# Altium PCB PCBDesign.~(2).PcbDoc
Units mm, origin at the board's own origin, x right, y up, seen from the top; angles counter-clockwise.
Board outline 60 x 50 mm, 2 copper layers (Top Layer, Bottom Layer); 10 components, 6 nets, 31 pads, 0 vias.
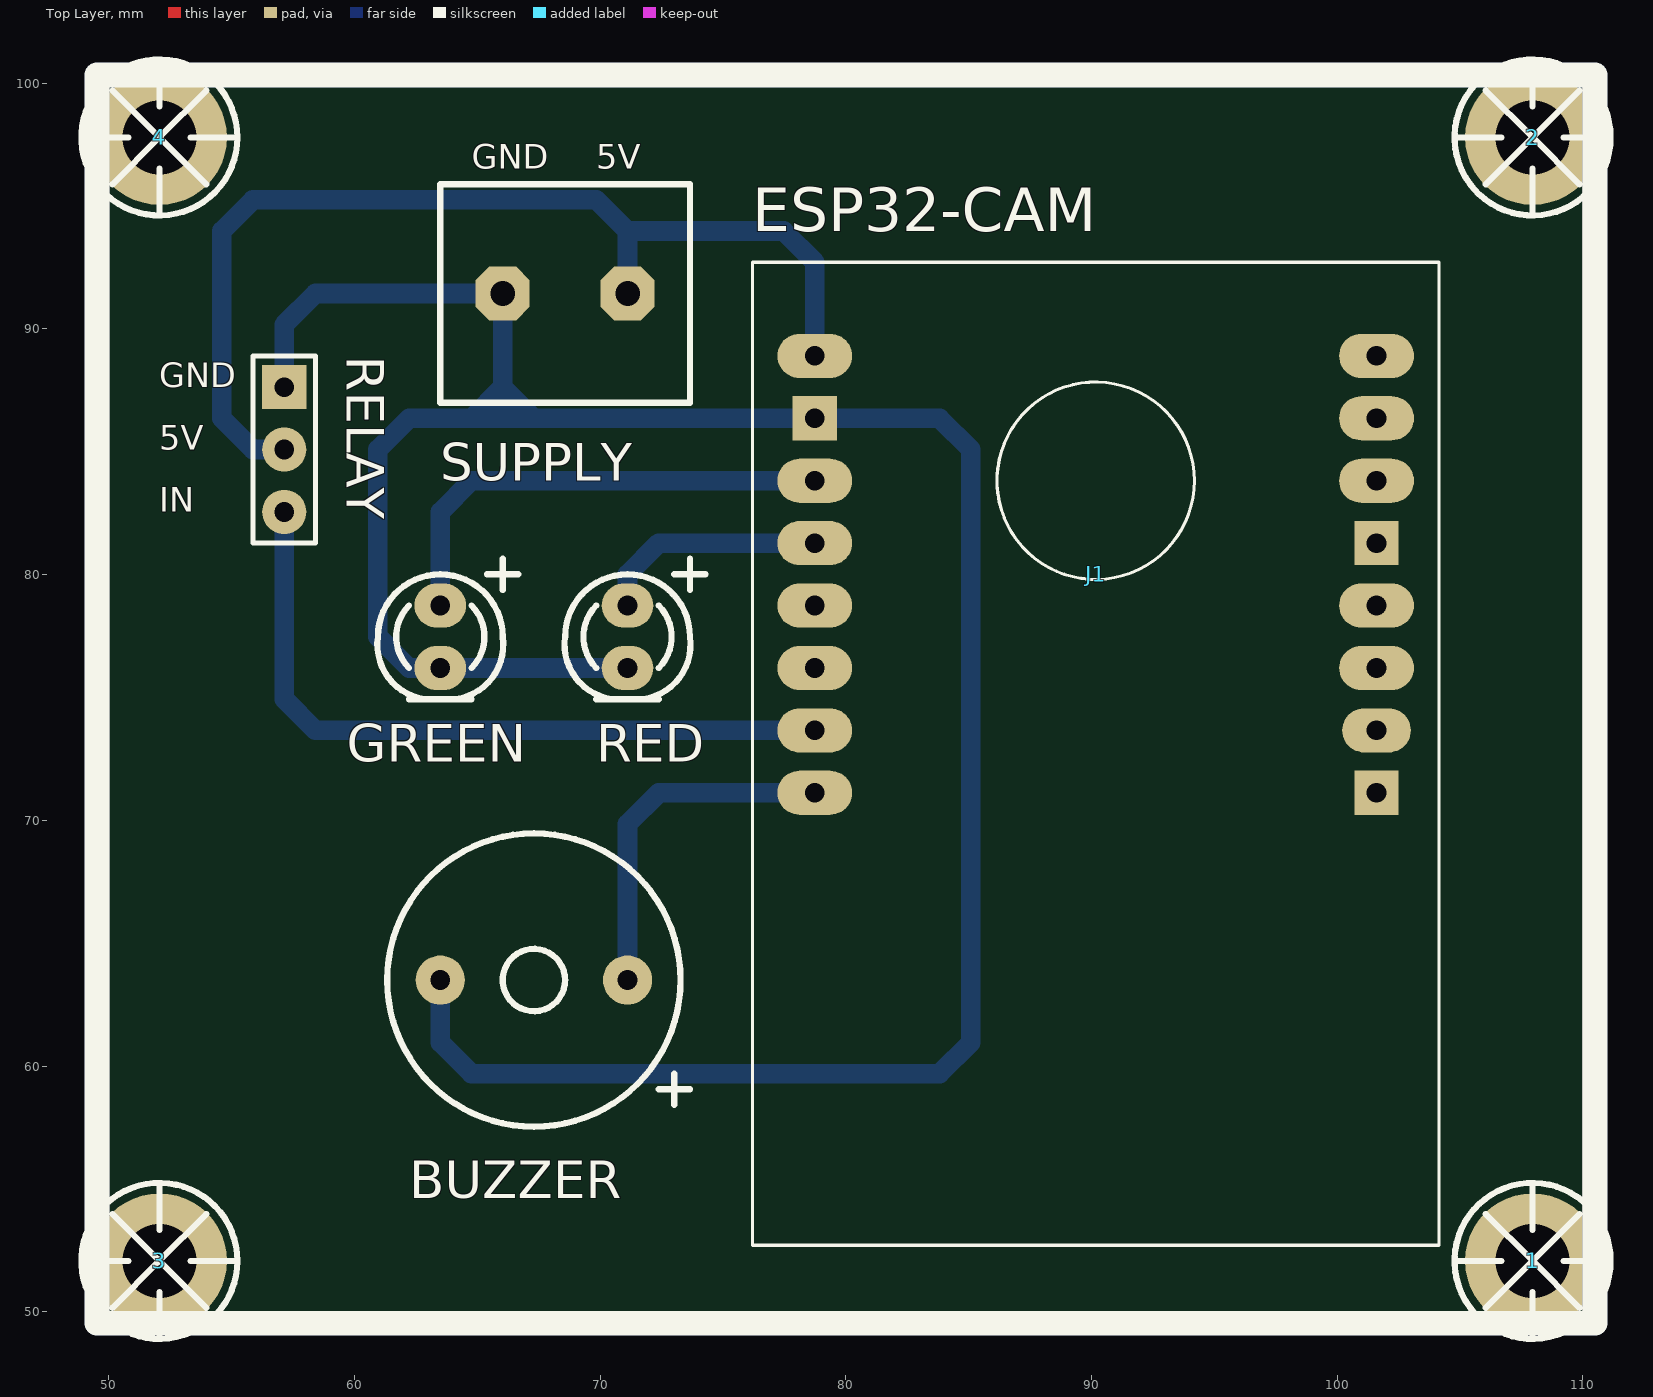
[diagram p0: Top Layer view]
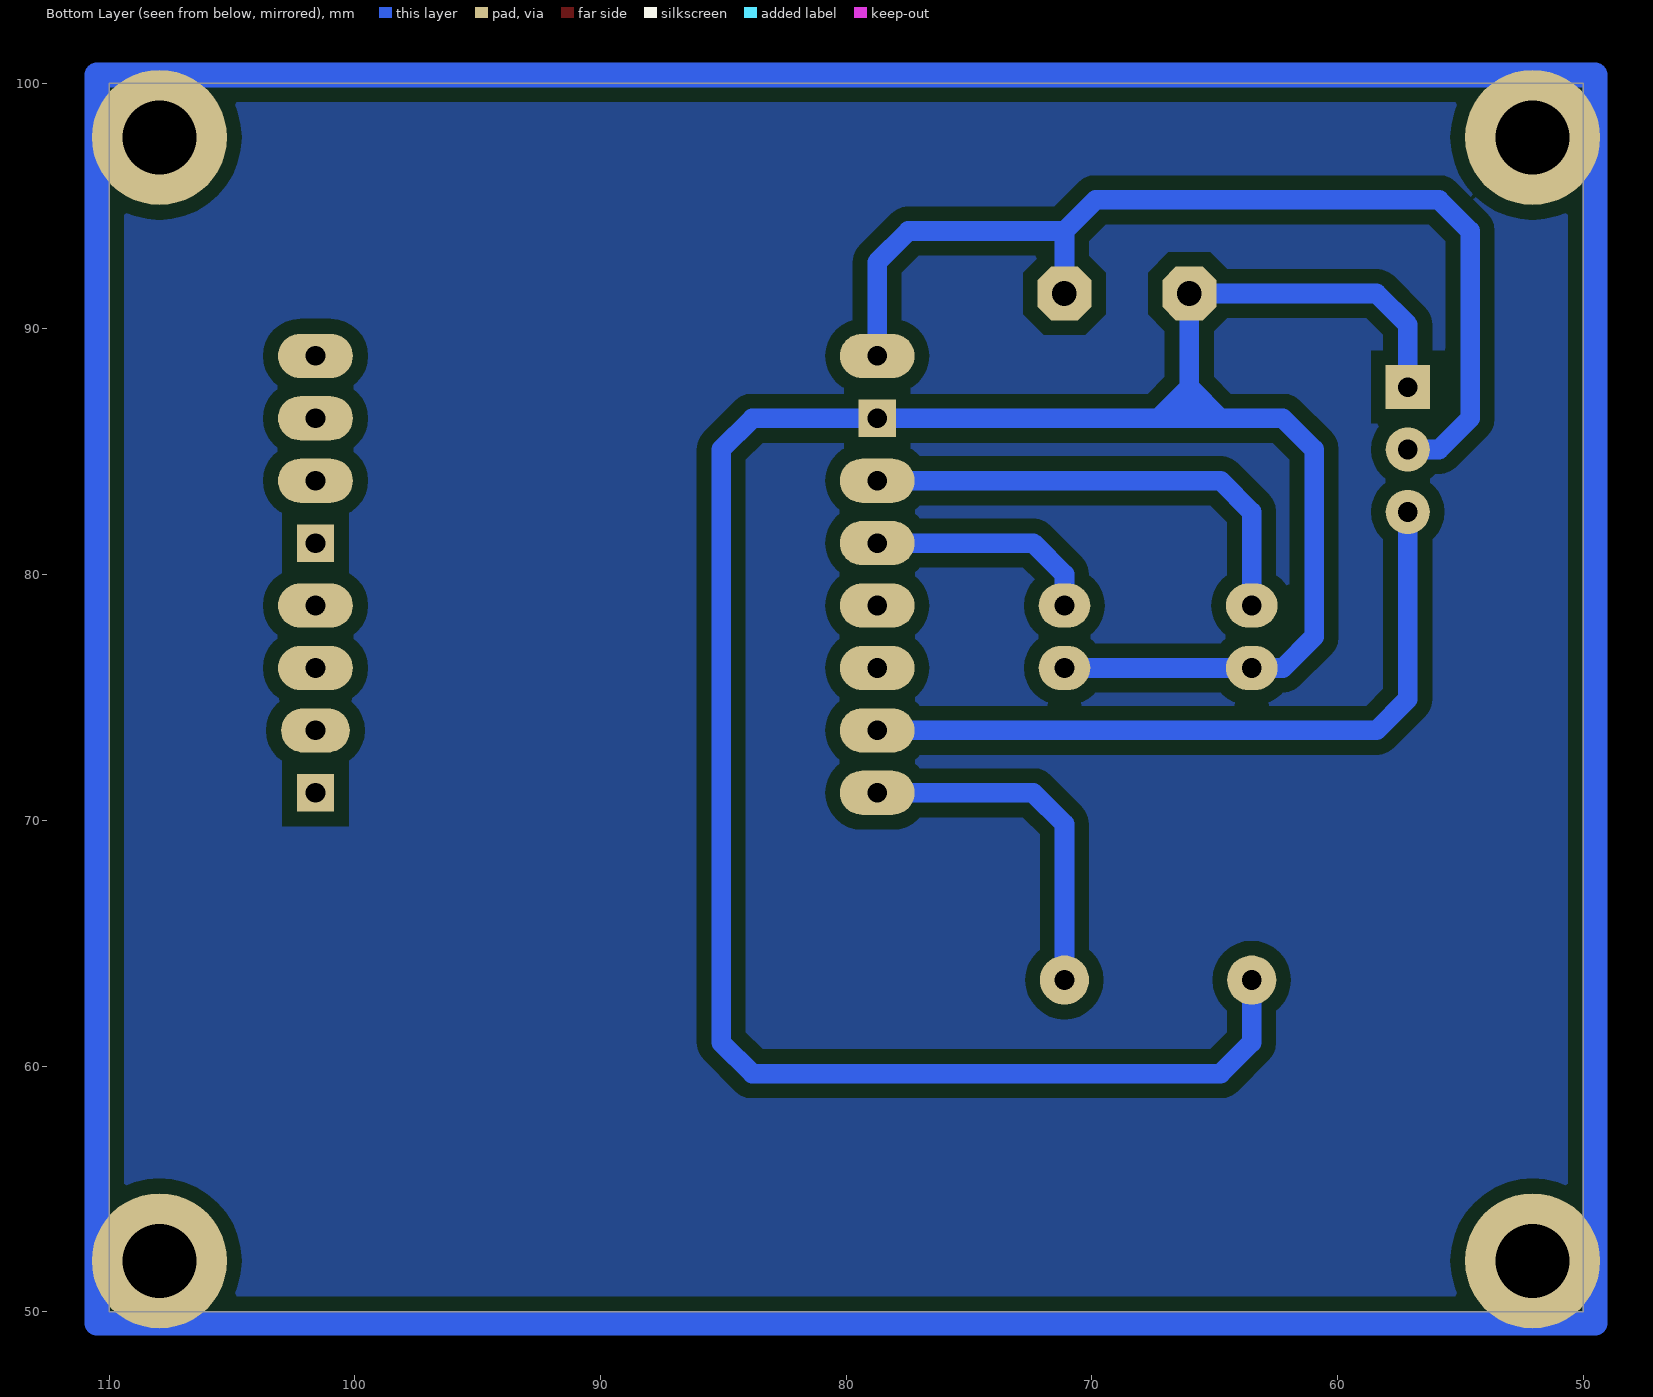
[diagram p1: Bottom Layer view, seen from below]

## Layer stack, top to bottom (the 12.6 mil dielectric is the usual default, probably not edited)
Top Solder: solder mask 0.0102, Solder Resist, Dk 3.5
Top Layer: signal copper 0.0356
Dielectric 1: dielectric 0.32, FR-4, Dk 4.8
Bottom Layer: signal copper 0.0356
Bottom Solder: solder mask 0.0102, Solder Resist, Dk 3.5

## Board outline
50,100 110,100 110,50 50,50 50,100

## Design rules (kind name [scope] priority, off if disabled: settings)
Clearance [All] p1: gap=0.6
PolygonConnect [All] p1: connectstyle=Relief reliefconductorwidth=0.254 reliefentries=4 polygonreliefangle="90 Angle" airgapwidth=0.254
RoutingLayers [All] p1: top layer_v5=FALSE bottom layer_v5=TRUE
RoutingVias [All] p1: holewidth=0.711 width=1.27 viastyle="Through Hole" minholewidth=0.711 minwidth=1.27 maxholewidth=0.711 maxwidth=1.27
SolderMaskExpansion [All] p1: expansion=0.102
Width [All] p1: maxlimit=1 minlimit=0.6 preferedwidth=0.8
29 further rules are at their usual default settings.

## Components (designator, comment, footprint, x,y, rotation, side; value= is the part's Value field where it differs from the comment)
1 "Spacer" Spacer 107.95,52.07 r90 top
2 "Spacer" Spacer 107.95,97.79 r90 top
3 "Spacer" Spacer 52.07,52.07 r90 top
4 "Spacer" Spacer 52.07,97.79 r90 top
BUZZER "Buzzer" BUZZER 67.31,63.5 r180 top (schematic designator LS1)
GREEN "LED-G" LED 63.5,78.74 r270 top (schematic designator D1)
J1 "ESP32-CAM" ESP32-CAM 90.17,78.74 r180 top
RED "LED-R" LED 71.12,78.74 r270 top (schematic designator D2)
RELAY "RELAY" HDR1X3 57.15,87.63 r270 top (schematic designator P1)
SUPPLY "SUPPLY" "Term.Block 2pin" 68.58,91.44 r0 top (schematic designator P2)

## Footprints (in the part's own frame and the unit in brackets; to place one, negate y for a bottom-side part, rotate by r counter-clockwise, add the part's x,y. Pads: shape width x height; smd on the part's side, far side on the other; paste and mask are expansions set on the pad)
BUZZER [mm]
  round 2 hole 0.8: 1(-3.81,0) 2(3.81,0)
  silkscreen extent -6.35,-5.97 5.97,5.97
ESP32-CAM [mm]
  rect 1.8x1.8 / inner round 1.524 / far side rect 1.524x1.524 hole 0.8: P$1(-11.43,7.62) P$5(-11.43,-2.54) P$10(11.43,-7.62)
  oval 2.8x1.8 hole 0.8: P$2(-11.43,5.08)
  oval 3.048x1.8 hole 0.8: P$3(-11.43,2.54) P$4(-11.43,0) P$6(-11.43,-5.08) P$7(-11.43,-7.62) P$8(-11.43,-10.16) P$9(11.43,-10.16) P$11(11.43,-5.08) P$12(11.43,-2.54) P$13(11.43,0) P$14(11.43,2.54) P$15(11.43,5.08) P$16(11.43,7.62)
  silkscreen extent -13.97,-13.97 13.97,26.04
HDR1X3 [mm] "Connector; Header; 3 Position"
  rect 1.8x1.8 hole 0.8: 1(0,0)
  round 1.8 hole 0.8: 2(2.54,0) 3(5.08,0)
  silkscreen extent -1.27,-1.27 6.35,1.27
LED [mm] "SMT LED; 2 Flat Leads"
  oval 1.8x2.1 hole 0.8: 1(0,0) 2(2.54,0)
  silkscreen extent -1.91,-2.56 3.81,3.17
Spacer [mm]
  round 5.5 hole 3: 0(0,0)
  silkscreen extent -3.17,-3.17 3.17,3.17
"Term.Block 2pin" [mm]
  oct 2.2x2.2 hole 1: 0(-2.54,0) 1(2.54,0)
  silkscreen extent -5.08,-4.44 5.08,4.44

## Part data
BUZZER: "Magnetic Transducer Buzzer"
GREEN RED: library part LED, "LED 3mm or 5mm"
J1: "ESP32 ESP32 Transceiver; 802.11 a/b/g/n (Wi-Fi, WiFi, WLAN), Bluetooth® Smart 4.x Low Energy (BLE) Evaluation Board"
RELAY: library part "Header 3", "Header, 3-Pin"
SUPPLY: library part "Terminal Block 2pin", "Terminal Block, 2-Pin"

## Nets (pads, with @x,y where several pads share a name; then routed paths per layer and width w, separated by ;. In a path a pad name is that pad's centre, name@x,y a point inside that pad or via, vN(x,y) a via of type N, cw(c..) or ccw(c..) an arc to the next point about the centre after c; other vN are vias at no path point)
BUZZER: BUZZER.1 J1.P$16 | length 14.5
  Bottom Layer w0.8: BUZZER.1 71.12,69.85 72.39,71.12 J1.P$16
GND: BUZZER.2 GREEN.2 J1.P$10 RED.2 RELAY.1 SUPPLY.0 | length 113.4
  Bottom Layer w0.8: RELAY.1 57.15,90.17 58.42,91.44 SUPPLY.0 66.04,87.63 ; BUZZER.2 63.5,60.96 64.77,59.69 83.82,59.69 85.09,60.96 85.09,85.09 83.82,86.36 J1.P$10 67.31,86.36 ; RED.2 GREEN.2 62.23,76.2 60.96,77.47 60.96,85.09 62.23,86.36 64.77,86.36 ; 64.77,86.36 66.04,86.36 ; 64.77,86.36 66.04,87.63 ; 66.04,86.36 67.31,86.36 ; 66.04,86.36 66.04,87.63 ; 66.04,87.63 67.31,86.36
LED-G: GREEN.1 J1.P$11 | length 19.6
  Bottom Layer w0.8: GREEN.1 63.5,82.55 64.77,83.82 J1.P$11
LED-R: J1.P$12 RED.1 | length 9.4
  Bottom Layer w0.8: RED.1 71.12,80.01 72.39,81.28 J1.P$12
RELAY: J1.P$15 RELAY.3 | length 29.7
  Bottom Layer w0.8: RELAY.3 57.15,74.93 58.42,73.66 J1.P$15
VCC: J1.P$9 RELAY.2 SUPPLY.1 | length 42.7
  Bottom Layer w0.8: RELAY.2 55.88,85.09 54.61,86.36 54.61,93.98 55.88,95.25 69.85,95.25 71.12,93.98 ; SUPPLY.1 71.12,93.98 ; J1.P$9 78.74,92.71 77.47,93.98 71.12,93.98
pads on no net: 1.0 2.0 3.0 4.0 J1.P$1 J1.P$2 J1.P$3 J1.P$4 J1.P$5 J1.P$6 J1.P$7 J1.P$8 J1.P$13 J1.P$14
copper on no net: | length 223.5
  Bottom Layer w1: 49.53,49.53 110.49,49.53 110.49,100.33 49.53,100.33 49.53,49.53

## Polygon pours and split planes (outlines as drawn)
no net on Bottom Layer "Top Layer-No Net" (solid, pour order 4): 49.53,100.33 49.53,49.53 110.49,49.53 110.49,100.33 49.53,100.33

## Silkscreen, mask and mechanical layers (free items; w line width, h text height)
Top Overlay:
  lines w1: 49.53,49.53 110.49,49.53 110.49,100.33 49.53,100.33 49.53,49.53
  text "GND" at 64.77,96.52 h1
  text "5V" at 69.85,96.52 h1
  text "GND" at 52.07,87.63 h1
  text "5V" at 52.07,85.09 h1
  text "IN" at 52.07,82.55 h1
